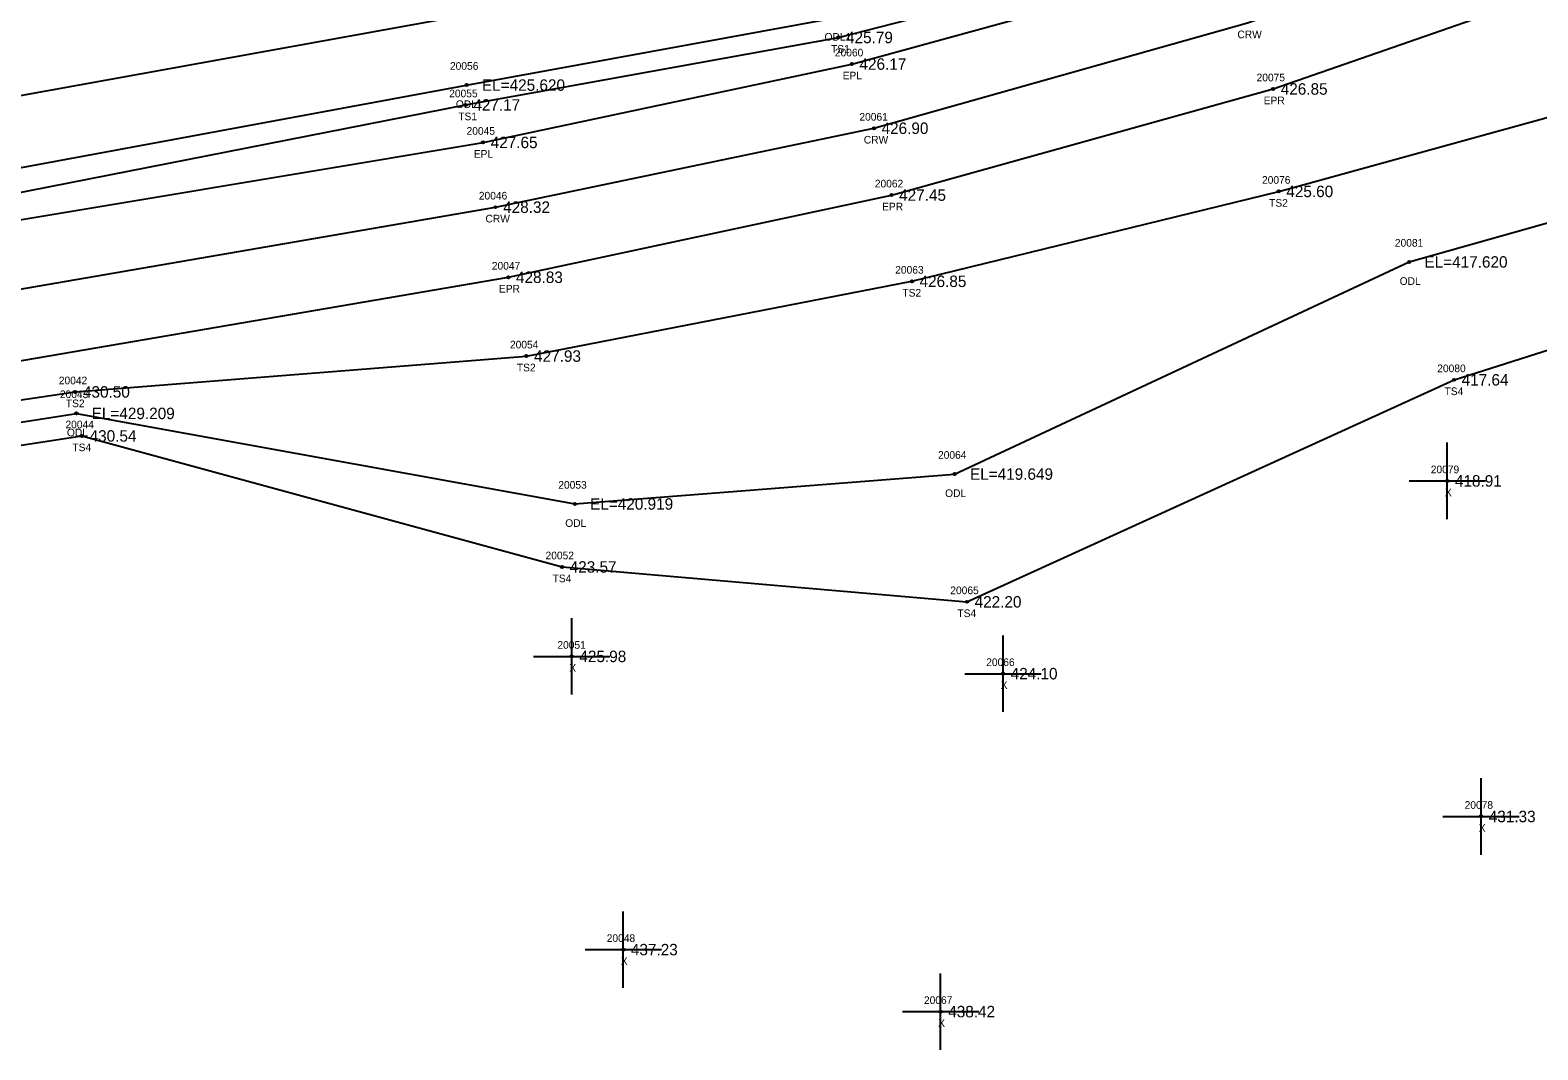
# Model space of a CAD drawing. Extents: x 2116373 to 2118139, y 979529 to 981026.
# Drawn here: x 2116558 to 2116755.3, y 979560.1 to 979693.5 of the extents above; entities that cross this region are included whole.
import ezdxf

# ---------------------------------------------------------------- set-up
doc = ezdxf.new("R2010")
doc.units = 0
for name, color, linetype in [('RD_DTM_BkLn1', 7, 'Continuous'), ('RD_DTM_BkLn2', 7, 'Continuous'), ('RD_DTM_BkLn_txCode', 7, 'Continuous'), ('RD_EX_H2O', 7, 'Continuous'), ('RD_EX_H2O_txCode', 7, 'Continuous'), ('RD_EX_Misc', 7, 'Continuous'), ('RD_EX_Misc_txCode', 7, 'Continuous'), ('RD_EX_Road', 7, 'Continuous'), ('RD_EX_Road_txCode', 7, 'Continuous'), ('RD_EX_TX_H2O_ELEV', 7, 'Continuous'), ('RD_EX_TX_Misc_ELEV', 7, 'Continuous'), ('RD_EX_TX_Road_ELEV', 7, 'Continuous'), ('RD_HC_Survey_ELEV', 7, 'Continuous'), ('RD_HC_Survey_txCode', 7, 'Continuous'), ('RD_SMD_Locator', 7, 'Continuous')]:
    doc.layers.add(name, color=color, linetype=linetype)

msp = doc.modelspace()

# ---------------------------------------------------------------- linework, layer by layer
at = {"layer": 'RD_DTM_BkLn1'}
msp.add_lwpolyline([(2116414.21, 979630.19), (2116468.62, 979643.23), (2116521.45, 979653.6), (2116618.87, 979670.38), (2116668.4, 979680.7), (2116717.3, 979694.48), (2116764.56, 979711.13), (2116810.15, 979729.38), (2116856.49, 979749.81), (2116900.74, 979773.15), (2116944.03, 979798.93), (2116982.75, 979824.6), (2117026.56, 979857.02), (2117064.34, 979888.81), (2117101.78, 979922.69), (2117176.3, 979989.4), (2117250.99, 980056.19), (2117326.56, 980126.36)], dxfattribs=at)
at = {"layer": 'RD_DTM_BkLn2'}
for points in [[(2116410.78, 979641.79), (2116465.45, 979654.97), (2116518.83, 979664.89), (2116614.96, 979683.75), (2116663.75, 979692.58), (2116713.02, 979705.22), (2116760.07, 979721.97), (2116804.88, 979741.47), (2116850.79, 979761.38), (2116894.83, 979783.88), (2116937.98, 979807.44), (2116977.39, 979833.6), (2117020.56, 979865.29), (2117056.86, 979896.38), (2117094.29, 979932.2), (2117168.14, 979997.38), (2117238.71, 980069.61), (2117312.33, 980134.21), (2117318.43, 980135.16)], [(2116408.48, 979653.74), (2116461.38, 979665.42), (2116520.7, 979678.48), (2116616.28, 979695.74), (2116661.37, 979703.79), (2116711.18, 979715.21), (2116757.77, 979732.03), (2116802.04, 979749.54), (2116847.76, 979769.63), (2116889.13, 979795.82), (2116931.32, 979820.72), (2116972.01, 979847.71), (2117009.67, 979877.33), (2117051.05, 979910.18), (2117086.71, 979942.74), (2117161.4, 980003.96), (2117222.13, 980080.24), (2117265.44, 980120.03)], [(2116417.57, 979618.2), (2116471.29, 979630.11), (2116523.91, 979640.31), (2116563.87, 979646.21), (2116622.92, 979650.9), (2116673.37, 979660.68), (2116721.38, 979672.44), (2116775.31, 979687.3), (2116820.23, 979708.52), (2116865.35, 979734.51), (2116907.21, 979760.29), (2116934.42, 979772.82), (2116951.5, 979788.78), (2116990.39, 979814.35), (2117033.97, 979847.22), (2117071.26, 979879.46), (2117111.32, 979914.45), (2117184.14, 979980.37), (2117264.18, 980040.84), (2117335.34, 980108.05), (2117336.43, 980115.6)], [(2116420.33, 979611.17), (2116472.25, 979624.85), (2116526.15, 979634.55), (2116564.74, 979640.45), (2116627.58, 979623.31), (2116680.58, 979618.75), (2116744.33, 979647.79), (2116783.58, 979660.27), (2116799.87, 979666.49), (2116808.73, 979670.75)]]:
    msp.add_lwpolyline(points, dxfattribs=at)
at = {"layer": 'RD_EX_H2O'}
for points in [[(2116411.09, 979644.42), (2116463.93, 979657.73), (2116517.88, 979668.38), (2116615.09, 979686.35), (2116663.35, 979695.16), (2116711.62, 979708.91), (2116758.49, 979726.13), (2116778.25, 979736.27), (2116803.5, 979744.47), (2116849.89, 979764.23), (2116894.14, 979786.32), (2116936.31, 979809.39), (2116976.21, 979834.9), (2117018.41, 979867.86), (2117054.24, 979898.91), (2117093.35, 979934.14), (2117166.11, 979999.69), (2117224.07, 980077.92), (2117265.44, 980120.03)], [(2116419.35, 979615.24), (2116471.51, 979627.15), (2116524.74, 979637.29), (2116564.01, 979643.4), (2116629.25, 979631.55), (2116678.97, 979635.46), (2116738.46, 979663.21), (2116776.82, 979674.03), (2116792.52, 979682.03), (2116799, 979683.75), (2116807.27, 979675.26), (2116829.37, 979675.94), (2116879.68, 979679.78), (2116933.5, 979668.89), (2116988.71, 979660.02), (2117093.78, 979621.95), (2117143.56, 979603.85), (2117167, 979599.31)]]:
    msp.add_lwpolyline(points, dxfattribs=at)
at = {"layer": 'RD_EX_Misc'}
for p, q in [((2116743.45, 979629.57), (2116743.45, 979639.57)), ((2116738.45, 979634.57), (2116748.45, 979634.57)), ((2116628.85, 979606.61), (2116628.85, 979616.61)), ((2116685.3, 979604.35), (2116685.3, 979614.35)), ((2116623.85, 979611.61), (2116633.85, 979611.61)), ((2116680.3, 979609.35), (2116690.3, 979609.35)), ((2116747.88, 979585.67), (2116747.88, 979595.67)), ((2116742.88, 979590.67), (2116752.88, 979590.67)), ((2116635.59, 979568.25), (2116635.59, 979578.25)), ((2116630.59, 979573.25), (2116640.59, 979573.25)), ((2116677.13, 979560.14), (2116677.13, 979570.14)), ((2116672.13, 979565.14), (2116682.13, 979565.14))]:
    msp.add_line(p, q, dxfattribs=at)
at = {"layer": 'RD_EX_Road'}
for points in [[(2116412.2, 979638.84), (2116468.17, 979651.36), (2116519.2, 979662.5), (2116617.24, 979678.85), (2116665.51, 979689.1), (2116714.23, 979702.46), (2116761.42, 979719.35), (2116806.99, 979737.42), (2116852.23, 979758.11), (2116896.57, 979780.91), (2116939.1, 979805.52), (2116978.46, 979832.1), (2117021.29, 979863.87), (2117058.15, 979895.61), (2117096.06, 979930.47), (2117170.14, 979995.71), (2117244.91, 980062.82), (2117320.63, 980133.49), (2117326.56, 980126.36)], [(2116416.36, 979621.21), (2116470.51, 979634.11), (2116523.97, 979644.68), (2116620.55, 979661.21), (2116670.7, 979671.96), (2116720.65, 979685.84), (2116767.66, 979702.22), (2116814.07, 979721.02), (2116860.35, 979742.3), (2116904.9, 979765.18), (2116949.06, 979791.19), (2116988.09, 979817.15), (2117031.94, 979849.78), (2117069.79, 979881.53), (2117108.89, 979916.38), (2117182.06, 979982.67), (2117257.56, 980049.29), (2117334.73, 980117.38), (2117326.56, 980126.36)]]:
    msp.add_lwpolyline(points, dxfattribs=at)
at = {"layer": 'RD_SMD_Locator'}
for centre in [(2116663.75, 979692.58), (2116665.51, 979689.1), (2116615.09, 979686.35), (2116720.65, 979685.84), (2116614.96, 979683.75), (2116668.4, 979680.7), (2116617.24, 979678.85), (2116670.7, 979671.96), (2116721.38, 979672.44), (2116618.87, 979670.38), (2116738.46, 979663.21), (2116620.55, 979661.21), (2116673.37, 979660.68), (2116622.92, 979650.9), (2116744.33, 979647.79), (2116563.87, 979646.21), (2116564.01, 979643.4), (2116564.74, 979640.45), (2116678.97, 979635.46), (2116743.45, 979634.57), (2116629.25, 979631.55), (2116627.58, 979623.31), (2116680.58, 979618.75), (2116628.85, 979611.61), (2116685.3, 979609.35), (2116747.88, 979590.67), (2116635.59, 979573.25), (2116677.13, 979565.14)]:
    msp.add_circle(centre, 0.15, dxfattribs=at)

# ---------------------------------------------------------------- texts
at = {"layer": 'RD_DTM_BkLn_txCode'}
for s, p in [('TS1', (2116662.79, 979690.58)), ('20055', (2116612.81, 979684.75)), ('TS1', (2116614, 979681.75)), ('20076', (2116719.2, 979673.44)), ('TS2', (2116720.13, 979670.44)), ('20063', (2116671.19, 979661.68)), ('TS2', (2116672.13, 979658.68)), ('20054', (2116620.76, 979651.9)), ('TS2', (2116621.67, 979648.9)), ('20080', (2116742.14, 979648.79)), ('20042', (2116561.71, 979647.21)), ('TS4', (2116743.09, 979645.79)), ('TS2', (2116562.63, 979644.21)), ('20044', (2116562.58, 979641.45)), ('TS4', (2116563.49, 979638.45)), ('20052', (2116625.42, 979624.31)), ('TS4', (2116626.34, 979621.31)), ('20065', (2116678.4, 979619.75)), ('TS4', (2116679.33, 979616.75))]:
    msp.add_text(s, height=1, dxfattribs=at).set_placement(p)
at = {"layer": 'RD_EX_H2O_txCode'}
for s, p in [('ODL1', (2116661.94, 979692.16)), ('20056', (2116612.91, 979688.35)), ('ODL1', (2116613.68, 979683.35)), ('20081', (2116736.59, 979665.21)), ('ODL', (2116737.22, 979660.21)), ('20043', (2116561.85, 979645.4)), ('ODL', (2116562.77, 979640.4)), ('20064', (2116676.79, 979637.46)), ('20053', (2116627.09, 979633.55)), ('ODL', (2116677.72, 979632.46)), ('ODL', (2116628, 979628.55))]:
    msp.add_text(s, height=1, dxfattribs=at).set_placement(p)
at = {"layer": 'RD_EX_Misc_txCode'}
for s, p in [('20079', (2116741.29, 979635.57)), ('X', (2116743.14, 979632.57)), ('20051', (2116626.97, 979612.61)), ('X', (2116628.53, 979609.61)), ('20066', (2116683.1, 979610.35)), ('X', (2116684.99, 979607.35)), ('20078', (2116745.72, 979591.67)), ('X', (2116747.57, 979588.67)), ('20048', (2116633.43, 979574.25)), ('X', (2116635.27, 979571.25)), ('20067', (2116674.95, 979566.14)), ('X', (2116676.81, 979563.14))]:
    msp.add_text(s, height=1, dxfattribs=at).set_placement(p)
at = {"layer": 'RD_EX_Road_txCode'}
for s, p in [('20060', (2116663.29, 979690.1)), ('EPL', (2116664.31, 979687.1)), ('20075', (2116718.49, 979686.84)), ('EPR', (2116719.42, 979683.84)), ('20045', (2116615.08, 979679.85)), ('EPL', (2116616.03, 979676.85)), ('20062', (2116668.52, 979672.96)), ('EPR', (2116669.47, 979669.96)), ('20047', (2116618.39, 979662.21)), ('EPR', (2116619.32, 979659.21))]:
    msp.add_text(s, height=1, dxfattribs=at).set_placement(p)
at = {"layer": 'RD_EX_TX_H2O_ELEV'}
for s, p in [('EL=425.620', (2116617.09, 979685.6)), ('EL=417.620', (2116740.46, 979662.46)), ('EL=429.209', (2116566.01, 979642.65)), ('EL=419.649', (2116680.97, 979634.71)), ('EL=420.919', (2116631.25, 979630.8))]:
    msp.add_text(s, height=1.5, dxfattribs=at).set_placement(p)
at = {"layer": 'RD_EX_TX_Misc_ELEV'}
for s, p in [('425.79', (2116664.75, 979691.83)), ('427.17', (2116615.96, 979683)), ('425.60', (2116722.38, 979671.69)), ('426.85', (2116674.37, 979659.93)), ('427.93', (2116623.92, 979650.15)), ('417.64', (2116745.33, 979647.04)), ('430.50', (2116564.87, 979645.46)), ('430.54', (2116565.74, 979639.7)), ('418.91', (2116744.45, 979633.82)), ('423.57', (2116628.58, 979622.56)), ('422.20', (2116681.58, 979618)), ('425.98', (2116629.85, 979610.86)), ('424.10', (2116686.3, 979608.6)), ('431.33', (2116748.88, 979589.92)), ('437.23', (2116636.59, 979572.5)), ('438.42', (2116678.13, 979564.39))]:
    msp.add_text(s, height=1.5, dxfattribs=at).set_placement(p)
at = {"layer": 'RD_EX_TX_Road_ELEV'}
for s, p in [('426.17', (2116666.51, 979688.35)), ('426.85', (2116721.65, 979685.09)), ('427.65', (2116618.24, 979678.1)), ('427.45', (2116671.7, 979671.21)), ('428.83', (2116621.55, 979660.46))]:
    msp.add_text(s, height=1.5, dxfattribs=at).set_placement(p)
at = {"layer": 'RD_HC_Survey_ELEV'}
for s, p in [('426.90', (2116669.4, 979679.95)), ('428.32', (2116619.87, 979669.63))]:
    msp.add_text(s, height=1.5, dxfattribs=at).set_placement(p)
at = {"layer": 'RD_HC_Survey_txCode'}
for s, p in [('CRW', (2116715.98, 979692.48)), ('20061', (2116666.5, 979681.7)), ('CRW', (2116667.08, 979678.7)), ('20046', (2116616.69, 979671.38)), ('CRW', (2116617.56, 979668.38))]:
    msp.add_text(s, height=1, dxfattribs=at).set_placement(p)

doc.saveas('drawing.dxf')
